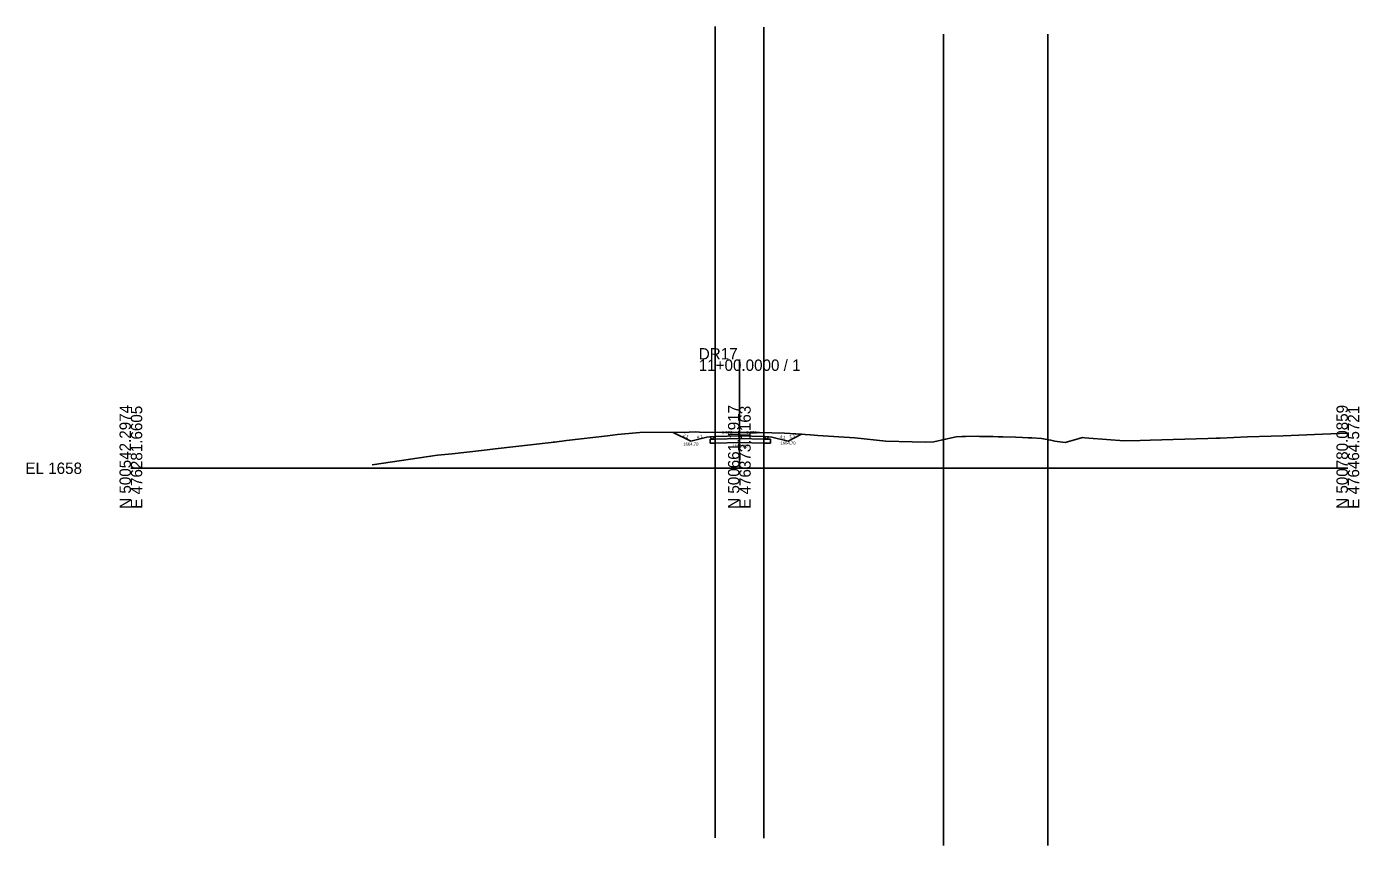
# Model space of a CAD drawing. Extents: x -26 to 303, y -96 to 3030.
# Drawn here: x -25.7 to 302.8, y 1907 to 2108.9 of the extents above; entities that cross this region are included whole.
import ezdxf

# ---------------------------------------------------------------- set-up
doc = ezdxf.new("R2010")
doc.units = 0
for name, color, linetype in [('Exist Cross Section Cell', 7, 'Continuous'), ('Exist XS Center Line Elevation Label', 7, 'Continuous'), ('Exist XS Ground Line', 7, 'Continuous'), ('Prop CMT Shallow Undercut Boundary', 7, 'Continuous'), ('Prop XS Ditch Slope Text', 7, 'Continuous'), ('Prop XS Ditch Standard Text', 7, 'Continuous'), ('Prop XS Earthwork Shape', 7, 'Continuous'), ('Prop XS EOT Tick Mark', 7, 'Continuous'), ('Prop XS Finish Grade', 7, 'Continuous'), ('Prop XS Finish Grade Earthwork', 7, 'Continuous'), ('Prop XS Finish Grade Pavement', 7, 'Continuous'), ('Prop XS Pvmt Edge Slope', 7, 'Continuous'), ('Prop XS SE Text', 7, 'Continuous'), ('Prop XS Shoulder Borrow Shape', 7, 'Continuous'), ('Prop XS Side Slope Text', 7, 'Continuous'), ('Prop XS Subgrade Earthwork', 7, 'Continuous'), ('Scratch_Level_2', 7, 'Continuous')]:
    doc.layers.add(name, color=color, linetype=linetype)

msp = doc.modelspace()

# ---------------------------------------------------------------- linework, layer by layer
at = {"layer": 'Exist Cross Section Cell'}
for p, q in [((150, 2000), (150, 2026.81)), ((0, 2000), (150, 2000)), ((150, 2000), (300, 2000))]:
    msp.add_line(p, q, dxfattribs=at)
at = {"layer": 'Exist XS Ground Line'}
msp.add_lwpolyline([(59.49, 2000.8), (59.5, 2000.8), (75.55, 2003.21), (79.22, 2003.54), (87.17, 2004.42), (89.81, 2004.76), (103.58, 2006.38), (104.07, 2006.42), (104.47, 2006.45), (107.4, 2006.84), (117.49, 2008.02), (119.98, 2008.28), (125.47, 2008.78), (137.65, 2008.88), (139.12, 2008.94), (140.2, 2008.87), (150, 2008.85), (154, 2008.85), (154.94, 2008.8), (161.14, 2008.61), (167.55, 2008.23), (169.36, 2008.08), (178.43, 2007.46), (186.14, 2006.71), (192.57, 2006.55), (195.92, 2006.45), (197.92, 2006.49), (200.83, 2007.14), (203.47, 2007.78), (204.84, 2007.82), (205.75, 2007.84), (208.65, 2007.87), (209.16, 2007.86), (209.83, 2007.86), (211.8, 2007.84), (212.6, 2007.81), (213.78, 2007.77), (214.18, 2007.76), (214.93, 2007.72), (218.07, 2007.64), (219.84, 2007.57), (221.22, 2007.51), (222.12, 2007.46), (224.45, 2007.34), (226.82, 2006.9), (227.81, 2006.71), (228.37, 2006.61), (230.31, 2006.37), (233.76, 2007.32), (234.62, 2007.58), (235.16, 2007.53), (236.15, 2007.44), (244.84, 2006.76), (248.83, 2006.86), (251.24, 2006.93), (265.47, 2007.35), (267.56, 2007.42), (268.5, 2007.45), (275.25, 2007.75), (281.12, 2007.89), (284.03, 2007.98), (293.74, 2008.43), (300, 2008.67)], dxfattribs=at)
at = {"layer": 'Prop CMT Shallow Undercut Boundary'}
for p, q in [((142.82, 2007.17), (144, 2007.19)), ((143.32, 2007.18), (142.82, 2007.17)), ((142.82, 2006.17), (142.82, 2007.17)), ((142.82, 2007.17), (142.82, 2006.17)), ((144, 2006.19), (142.82, 2006.17)), ((142.82, 2006.17), (144, 2006.19)), ((144, 2007.19), (143.32, 2007.18)), ((144, 2007.19), (150, 2007.31)), ((150, 2007.31), (144, 2007.19)), ((150, 2006.31), (144, 2006.19)), ((144, 2006.19), (150, 2006.31)), ((150, 2007.31), (156, 2007.19)), ((156, 2007.19), (150, 2007.31)), ((156, 2006.19), (150, 2006.31)), ((150, 2006.31), (156, 2006.19)), ((156, 2007.19), (157.68, 2007.16)), ((157.68, 2006.16), (156, 2006.19)), ((156, 2006.19), (157.68, 2006.16)), ((157.68, 2007.16), (157.68, 2006.16)), ((157.68, 2006.16), (157.68, 2007.16))]:
    msp.add_line(p, q, dxfattribs=at)
msp.add_lwpolyline([(157.68, 2007.16), (156.68, 2007.18), (156, 2007.19)], dxfattribs=at)
at = {"layer": 'Prop XS Earthwork Shape'}
msp.add_lwpolyline([(142, 2007.7), (138, 2006.7), (133.71, 2008.84), (137.65, 2008.88), (139.12, 2008.94), (140.2, 2008.87), (150, 2008.85), (154, 2008.85), (154.94, 2008.8), (161.14, 2008.61), (165.33, 2008.36), (162, 2006.7), (158, 2007.7), (157.26, 2007.76), (156.68, 2007.18), (156, 2007.19), (150, 2007.31), (144, 2007.19), (143.32, 2007.18), (142.74, 2007.76)], close=True, dxfattribs=at)
at = {"layer": 'Prop XS EOT Tick Mark'}
for p, q in [((144, 2007.86), (144, 2008.86)), ((156, 2007.86), (156, 2008.86))]:
    msp.add_line(p, q, dxfattribs=at)
at = {"layer": 'Prop XS Finish Grade'}
for p, q in [((144, 2007.86), (142.74, 2007.76)), ((156, 2007.86), (157.26, 2007.76))]:
    msp.add_line(p, q, dxfattribs=at)
at = {"layer": 'Prop XS Finish Grade Earthwork'}
for p, q in [((138, 2006.7), (133.71, 2008.84)), ((142, 2007.7), (138, 2006.7)), ((142.74, 2007.76), (142, 2007.7)), ((157.26, 2007.76), (158, 2007.7)), ((158, 2007.7), (162, 2006.7)), ((162, 2006.7), (165.33, 2008.36))]:
    msp.add_line(p, q, dxfattribs=at)
at = {"layer": 'Prop XS Finish Grade Pavement'}
for p, q in [((144, 2007.86), (150, 2007.98)), ((150, 2007.98), (156, 2007.86))]:
    msp.add_line(p, q, dxfattribs=at)
at = {"layer": 'Prop XS Pvmt Edge Slope'}
for p, q in [((144, 2007.86), (143.32, 2007.18)), ((156, 2007.86), (156.68, 2007.18))]:
    msp.add_line(p, q, dxfattribs=at)
at = {"layer": 'Prop XS Shoulder Borrow Shape'}
for points in [[(144, 2007.86), (143.32, 2007.18), (142.74, 2007.76)], [(156.68, 2007.18), (157.26, 2007.76), (156, 2007.86)]]:
    msp.add_lwpolyline(points, close=True, dxfattribs=at)
at = {"layer": 'Prop XS Subgrade Earthwork'}
for p, q in [((143.32, 2007.18), (142.74, 2007.76)), ((156.68, 2007.18), (157.26, 2007.76)), ((144, 2007.19), (143.32, 2007.18)), ((150, 2007.31), (144, 2007.19)), ((156, 2007.19), (150, 2007.31)), ((156, 2007.19), (156.68, 2007.18))]:
    msp.add_line(p, q, dxfattribs=at)
at = {"layer": 'Scratch_Level_2'}
for p, q in [((144, 2108.86), (144, 1908.86)), ((156, 2108.77), (156, 1908.77)), ((200.35, 2107.03), (200.35, 1907.03)), ((226.08, 2107.03), (226.08, 1907.03))]:
    msp.add_line(p, q, dxfattribs=at)

# ---------------------------------------------------------------- texts
at = {"layer": 'Exist Cross Section Cell'}
for s, p in [('DR17', (140, 2026.81)), ('11+00.0000 / 1', (140, 2024.01)), ('EL 1658', (-26, 1998.6))]:
    msp.add_text(s, height=2.8, dxfattribs=at).set_placement(p)
for s, p in [('N 500542.2974', (0, 1990)), ('E 476281.6605', (2.8, 1990)), ('N 500661.1917', (150, 1990)), ('E 476373.1163', (152.8, 1990)), ('N 500780.0859', (300, 1990)), ('E 476464.5721', (302.8, 1990))]:
    msp.add_text(s, height=2.8, rotation=90, dxfattribs=at).set_placement(p)
at = {"layer": 'Exist XS Center Line Elevation Label'}
msp.add_text('1666.85', height=0.75, dxfattribs=at).set_placement((148.26, 2005.07))
at = {"layer": 'Prop XS Ditch Slope Text'}
for rotation, p in [(14.0362, (139.61, 2007.23)), (345.9638, (159.87, 2007.48))]:
    msp.add_text('4:1', height=0.75, rotation=rotation, dxfattribs=at).set_placement(p)
at = {"layer": 'Prop XS Ditch Standard Text'}
for p in [(136.16, 2005.59), (160.12, 2005.84)]:
    msp.add_text('1664.70', height=0.75, dxfattribs=at).set_placement(p)
at = {"layer": 'Prop XS SE Text'}
for rotation, p in [(1.1458, (145.71, 2008.39)), (358.8542, (151.71, 2008.45))]:
    msp.add_text('0.020', height=0.75, rotation=rotation, dxfattribs=at).set_placement(p)
at = {"layer": 'Prop XS Side Slope Text'}
for rotation, p in [(333.4349, (135.98, 2007.95)), (26.5651, (162.54, 2007.3))]:
    msp.add_text('2:1', height=0.75, rotation=rotation, dxfattribs=at).set_placement(p)

doc.saveas('drawing.dxf')
